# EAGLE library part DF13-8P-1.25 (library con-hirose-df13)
DF13-8P 1.25mm Pitch Miniature Crimping Connector.
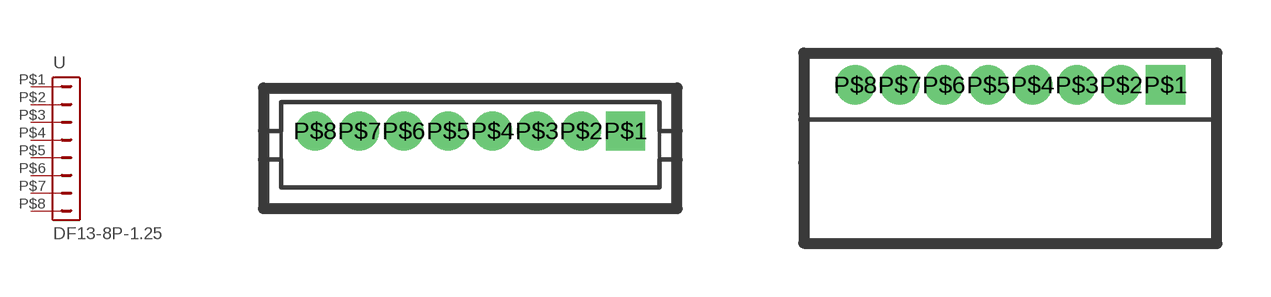
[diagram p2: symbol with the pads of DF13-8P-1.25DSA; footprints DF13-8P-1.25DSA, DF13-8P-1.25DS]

Designator prefix -

## DF13-8P-1.25DSA  [DF13-8P-1.25DSA]
P$1  1  pas
P$2  2  pas
P$3  3  pas
P$4  4  pas
P$5  5  pas
P$6  6  pas
P$7  7  pas
P$8  8  pas

## DF13-8P-1.25DS  [DF13-8P-1.25DS]
Pads as for DF13-8P-1.25DSA

## DF13-8P-1.25V  [DF13C-8P-1.25V]
Pads as for DF13-8P-1.25DSA

## DF13-8P-1.25H  [DF13A-8P-1.25H]
Pads as for DF13-8P-1.25DSA

## Footprint DF13-8P-1.25DSA (pad centres in mm)
Single Row Straight Pin Header (Through hole)
drill 0.6 pad 1.016 square: P$1 4.375,0
drill 0.6 pad 1.016 round: P$2 3.125,0; P$3 1.875,0; P$4 0.625,0; P$5 -0.625,0; P$6 -1.875,0; P$7 -3.125,0; P$8 -4.375,0

## Footprint DF13-8P-1.25DS (pad centres in mm)
Single Row Right Angle Pin Header (Through hole)
drill 0.6 pad 1.016 square: P$1 4.375,0
drill 0.6 pad 1.016 round: P$2 3.125,0; P$3 1.875,0; P$4 0.625,0; P$5 -0.625,0; P$6 -1.875,0; P$7 -3.125,0; P$8 -4.375,0

## Footprint DF13C-8P-1.25V (pad centres in mm)
Single Row Straight Pin Header (SMT)
smd 1.6 x 2.2: M$0 6.825,-1.8; M$1 -6.825,-1.8
smd 0.7 x 1.8: P$1 -4.375,0.9; P$2 -3.125,0.9; P$3 -1.875,0.9; P$4 -0.625,0.9; P$5 0.625,0.9; P$6 1.875,0.9; P$7 3.125,0.9; P$8 4.375,0.9

## Footprint DF13A-8P-1.25H (pad centres in mm)
Single Row Straight Pin Header (SMT)
smd 1.6 x 2.2: M$0 -6.725,2.4; M$1 6.725,2.4
smd 0.7 x 1.8: P$1 -4.375,-0.9; P$2 -3.125,-0.9; P$3 -1.875,-0.9; P$4 -0.625,-0.9; P$5 0.625,-0.9; P$6 1.875,-0.9; P$7 3.125,-0.9; P$8 4.375,-0.9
